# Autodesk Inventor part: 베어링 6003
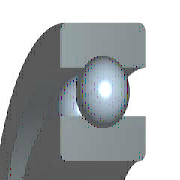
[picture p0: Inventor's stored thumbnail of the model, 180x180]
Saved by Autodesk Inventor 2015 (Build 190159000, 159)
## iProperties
Created: 2012-02
Part Number: 베어링 6003
Material: 강철, 연강
Description: 깊은 그루브 볼 베어링
Document SubType Name: Modeling
Standard: KS B 2023
Designer: mduedu
Standards Organization: KS
Language: ko-KR
Size Designation: 6003 - 17 x 35 x 10
Categories: <MemberInstance><Categories><Category DisplayName="샤프트 부품" InternalName="7f7aeb1f-a693-4053-b835-cee3144e0d98" Mnemonic="SHFT"><Category DisplayName="베어링" Inter
Density: 1 g/cm^3
Appearance: Steel
IsCustomPart: 1
Author: mduedu
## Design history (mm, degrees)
sketch "스케치" dims "d0" = 4.68 (= -0.26 x WD + 0.26 x BD)
  geometry: L1 (2.66, 13)-(7.34, 13); L2 (5, 13)-(5, 10.66); L3 (5, 13)-(5, 15.34); L4 (3.261, 11.434)-(0, 11.434); L5 (0, 8.5)-(10, 8.5); L6 (3.261, 14.566)-(0, 14.566); L7 (0, 17.5)-(10, 17.5); L8 (10, 8.5)-(10, 11.434); L9 (6.739, 11.434)-(10, 11.434); L10 (6.739, 14.566)-(10, 14.566); L11 (10, 17.5)-(10, 14.566); L12 (-1.4, 0)-(8.4, 0) reference; L13 (0, -0.3)-(0, 5.3) reference
  constraints: 22 end point, 4 point on line, 2 collinear, 2 perpendicular, 2 symmetric about line, 1 midpoint, 1 parallel, 14 other
  dimensions: "d9" = 17 diameter of L5 L12 (= WD); "d11" = 35 diameter of L7 L12 (= BD); "d12" = 10 distance between parallel lines of L8 L13 (= KB); "d13" = 22.868 diameter of L9 L12 (= 0.326 x BD + 0.674 x WD)
revolve "본체" stored, may be unused: angle "d6" = 90 deg
revolve "볼" stored, may be unused: angle "d7" = 90 deg
pattern_circular "IDS_ARRAYBALL[SIMPL:T]" dims angle "d3" = 360 deg
body "Solid1"
fillet "모깎기1" dims "d1" = 0.3 (= KRS)
other parameters: "WD" = 17 [user parameter; used in 5 equation terms], "BD" = 35 [user parameter; used in 5 equation terms], "KB" = 10 [user parameter; used in 1 equation term], "KRS" = 0.3 [user parameter; used in 1 equation term], "d4" = 0, "d5" = 0, "d8" = 0, "d14" = 0, "d15" = 0, "BBA" = 0 [user parameter], "BC0" = 3250000 [user parameter], "BC" = 6050000 [user parameter], "BR" = 17.5 (= 0.5 x BD) [user parameter], "WR" = 8.5 (= 0.5 x WD) [user parameter]
